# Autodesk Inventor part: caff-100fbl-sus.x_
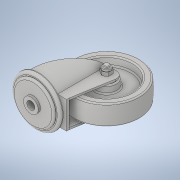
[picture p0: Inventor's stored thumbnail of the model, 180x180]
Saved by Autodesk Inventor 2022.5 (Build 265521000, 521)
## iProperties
Created: 2021-10
Part Number: caff-100fbl-sus.x_
Material: 一般
Document SubType Name: Modeling
Designer: ImaoCorp
Density: 1 g/cm^3
Appearance: 既定
Sending System: SOLIDWORKS 2019-2019304
MC: AMD64
MC_MODEL: Intel64 Family 6 Model 60 Stepping 3, GenuineIntel
OS: Windows_NT
FRU: Parasolid Version 31.0, build 290,  9- 1-2019
FORMAT: text
GUISE: transmit
KEY: caff-100fbl-sus
FILE: caff-100fbl-sus.x_t
DATE: Tue Oct 19 08:25:39 2021
Author: ImaoCorp
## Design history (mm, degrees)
feature "Base1"
node "ソリッド1"
